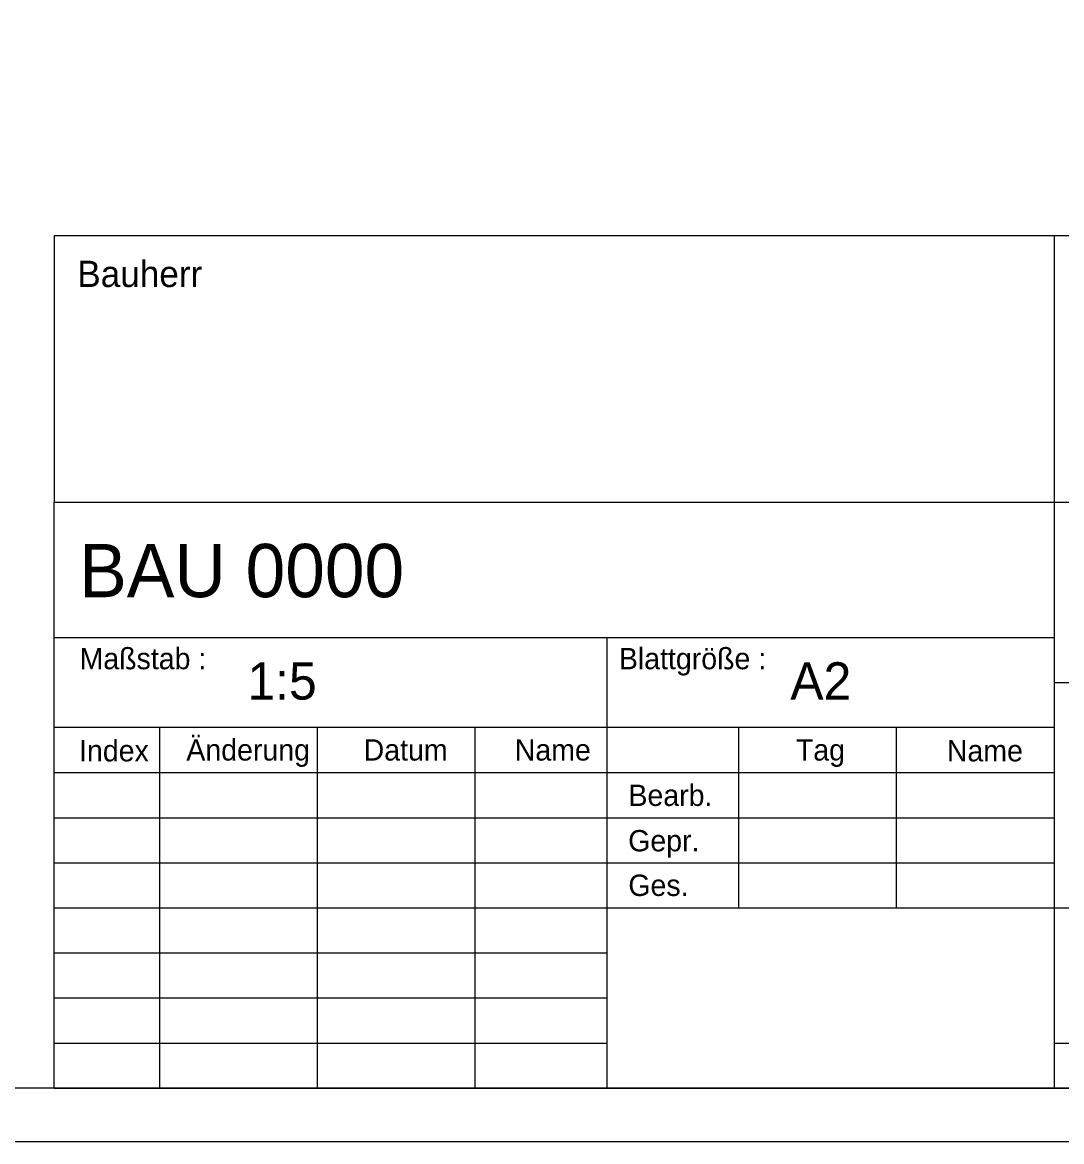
# Model space of a CAD drawing. Extents: x 0 to 2.97, y 0 to 2.1.
# Drawn here: x 2.041 to 2.528, y 0 to 0.525 of the extents above; entities that cross this region are included whole.
import ezdxf

# ---------------------------------------------------------------- set-up
doc = ezdxf.new("R2010")
doc.units = 0
doc.layers.add('90_Plankopf', color=7, linetype='Continuous')

msp = doc.modelspace()

# ---------------------------------------------------------------- linework, layer by layer
at = {"layer": '90_Plankopf'}
for p, q in [((2.945, 0.42495), (2.0556, 0.42495)), ((2.0556, 0.42495), (2.0556, 0.29995)), ((2.525, 0.29995), (2.525, 0.42495)), ((2.0556, 0.29995), (2.945, 0.29995)), ((2.0556, 0.025), (2.0556, 0.29995)), ((2.0556, 0.29995), (2.945, 0.29995)), ((2.525, 0.025), (2.525, 0.29995)), ((2.0556, 0.2365), (2.525, 0.2365)), ((2.31501, 0.025), (2.31501, 0.2365)), ((2.525, 0.21535), (2.945, 0.21535)), ((2.0556, 0.19435), (2.525, 0.19435)), ((2.10501, 0.1942), (2.10501, 0.025)), ((2.17913, 0.025), (2.17913, 0.1942)), ((2.25324, 0.025), (2.25324, 0.1942)), ((2.37677, 0.1942), (2.37677, 0.1096)), ((2.45089, 0.1096), (2.45089, 0.1942)), ((2.0556, 0.17315), (2.525, 0.17315)), ((2.0556, 0.1519), (2.525, 0.1519)), ((2.0556, 0.13075), (2.525, 0.13075)), ((2.0556, 0.1096), (2.525, 0.1096)), ((2.0556, 0.1096), (2.525, 0.1096)), ((2.31501, 0.1096), (2.525, 0.1096)), ((2.525, 0.1096), (2.945, 0.1096)), ((2.31501, 0.08845), (2.0556, 0.08845)), ((2.31501, 0.0673), (2.0556, 0.0673)), ((2.0556, 0.04615), (2.31501, 0.04615)), ((2.525, 0.04615), (2.945, 0.04615)), ((2.945, 0.025), (2.0556, 0.025)), ((2.0556, 0.025), (2.31501, 0.025)), ((2.114, 0.025), (2.945, 0.025)), ((2.114, 0.025), (2.945, 0.025))]:
    msp.add_line(p, q, dxfattribs=at)
for points in [[(0, 0), (2.97, 0), (2.97, 2.1), (0, 2.1)], [(0.125, 2.075), (2.945, 2.075), (2.945, 0.025), (0.125, 0.025)]]:
    msp.add_lwpolyline(points, close=True, dxfattribs=at)

# ---------------------------------------------------------------- texts
for s, height, p in [('Bauherr', 0.012318, (2.06651, 0.40087)), ('BAU 0000      ', 0.025, (2.06745, 0.25537)), ('Maßstab :', 0.01, (2.06758, 0.22158)), ('Blattgröße :', 0.0099995, (2.32058, 0.22158)), ('1:5      ', 0.0175, (2.14631, 0.20734)), ('A2       ', 0.0175, (2.401, 0.20734)), ('Änderung', 0.01, (2.11767, 0.17874)), ('Index', 0.01, (2.06734, 0.17836)), ('Datum', 0.01, (2.20084, 0.17874)), ('Name', 0.01, (2.27174, 0.17874)), ('Tag', 0.01, (2.40361, 0.17874)), ('Name', 0.01, (2.47445, 0.17836)), ('Bearb.', 0.01, (2.32507, 0.15745)), ('Gepr.', 0.01, (2.32495, 0.13615)), ('Ges.', 0.01, (2.32502, 0.11523))]:
    msp.add_text(s, height=height, dxfattribs=at).set_placement(p)

doc.saveas('drawing.dxf')
